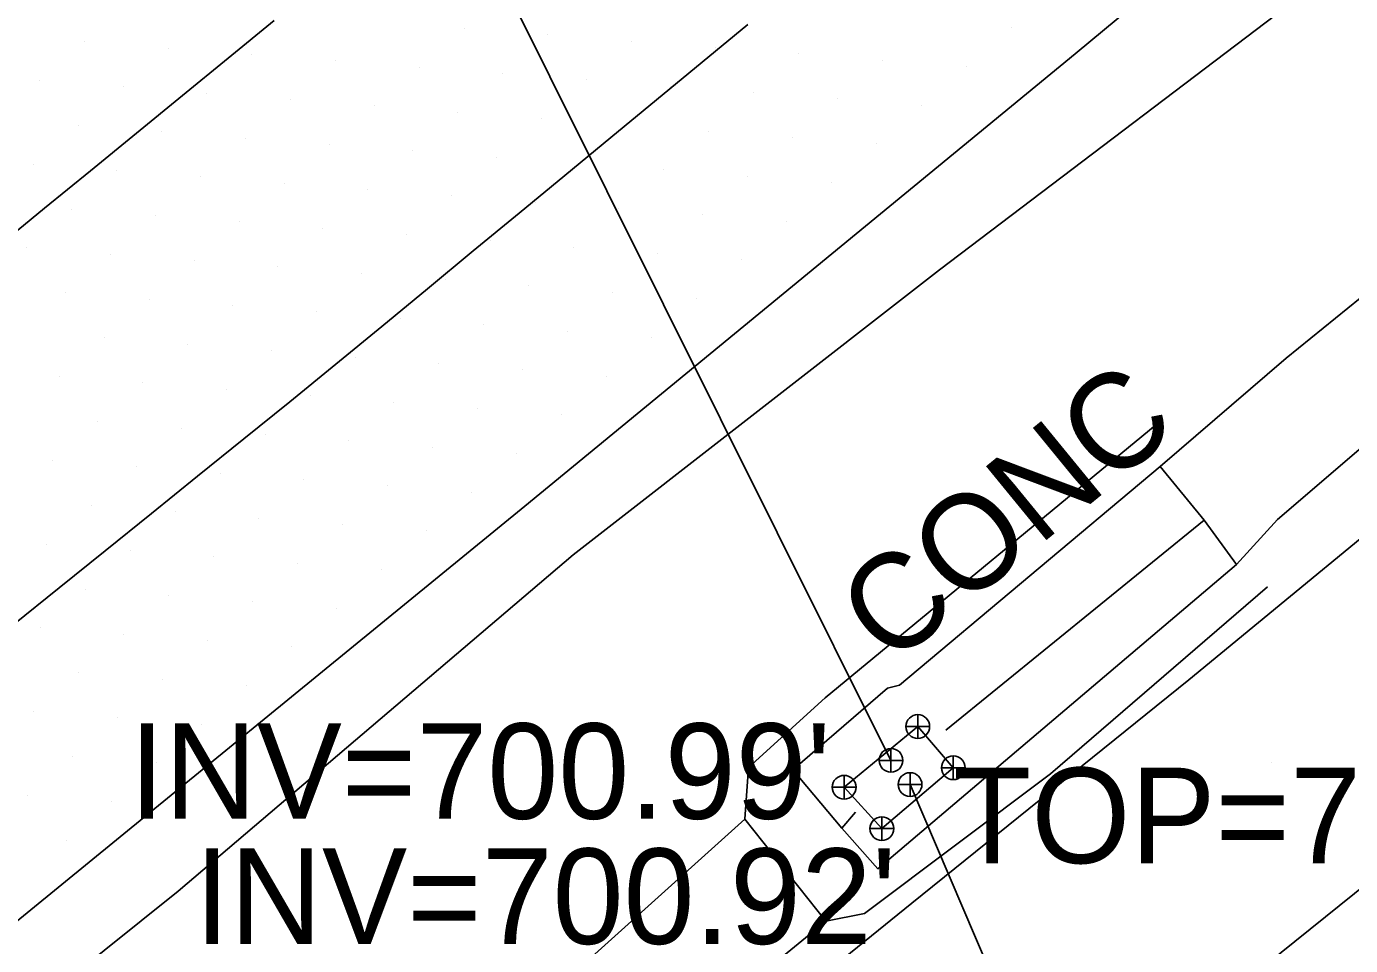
# Model space of a CAD drawing. Extents: x 1548934 to 1561348, y 809680 to 824075.
# Drawn here: x 1551457.5 to 1551513.3, y 810442.3 to 810481 of the extents above; entities that cross this region are included whole.
import ezdxf

# ---------------------------------------------------------------- set-up
doc = ezdxf.new("R2010")
doc.units = 0
for name, color, linetype in [('Default', 7, 'Continuous'), ('E_NCDOT_Vertical_Profile_Ground_Line', 7, 'Continuous'), ('Exist DTM QL2 LIDAR Elevation Point', 7, 'Continuous'), ('Exist DTM Scan Elevation Point', 7, 'Continuous'), ('Exist Guardrail Cable Guide Rail', 7, 'Continuous'), ('Exist Structure Minor Drop Inlet Top Elevation', 7, 'Continuous'), ('Exist Structure Minor Paved Ditch or Gutter', 7, 'Continuous'), ('Exist Structure Minor Paved Ditch or Gutter Text', 7, 'Continuous'), ('Exist Structure Minor Pipes RCP 15 Inch Invert Elevation', 7, 'Continuous'), ('P_RDY_Dimension', 7, 'Continuous'), ('P_RDY_Terminator_Cell', 7, 'Continuous'), ('PH Exist DTM Breakline', 7, 'Continuous'), ('Sheet_Matchline_Text', 7, 'Continuous')]:
    doc.layers.add(name, color=color, linetype=linetype)

# ---------------------------------------------------------------- blocks, each defined once
blk = doc.blocks.new('SurveyPointCell')
at = {"layer": 'Default'}
for p, q in [((-0.5, 0), (0.5, 0)), ((0, -0.5), (0, 0.5))]:
    blk.add_line(p, q, dxfattribs=at)
blk.add_circle((0, 0), 0.5, dxfattribs=at)

msp = doc.modelspace()

# ---------------------------------------------------------------- linework, layer by layer
at = {"layer": 'E_NCDOT_Vertical_Profile_Ground_Line'}
msp.add_lwpolyline([(1551420.508, 810413.559), (1551431.924, 810422.797), (1551455.236, 810441.768), (1551478.523, 810460.78), (1551501.702, 810479.825), (1551524.839, 810499.022), (1551547.879, 810518.234), (1551570.873, 810537.502), (1551593.819, 810556.903), (1551616.71, 810576.292), (1551639.811, 810595.486)], dxfattribs=at)
at = {"layer": 'Exist DTM QL2 LIDAR Elevation Point'}
for p, q in [((1551479.977, 810449.967), (1551479.977, 810449.967)), ((1551509.98, 810449.967), (1551509.98, 810449.967))]:
    msp.add_line(p, q, dxfattribs=at)
at = {"layer": 'Exist DTM Scan Elevation Point'}
for p, q in [((1551475.968, 810480.891), (1551475.968, 810480.891)), ((1551479.493, 810480.623), (1551479.493, 810480.623)), ((1551499.018, 810480.915), (1551499.018, 810480.915)), ((1551459.971, 810480.332), (1551459.971, 810480.332)), ((1551463.496, 810480.064), (1551463.496, 810480.064)), ((1551483.019, 810480.355), (1551483.019, 810480.355)), ((1551486.544, 810480.088), (1551486.544, 810480.088)), ((1551467.021, 810479.797), (1551467.021, 810479.797)), ((1551470.546, 810479.529), (1551470.546, 810479.529)), ((1551490.069, 810479.82), (1551490.069, 810479.82)), ((1551493.595, 810479.553), (1551493.595, 810479.553)), ((1551474.072, 810479.262), (1551474.072, 810479.262)), ((1551477.597, 810478.994), (1551477.597, 810478.994)), ((1551497.121, 810479.286), (1551497.121, 810479.286)), ((1551458.074, 810478.703), (1551458.074, 810478.703)), ((1551461.6, 810478.435), (1551461.6, 810478.435)), ((1551481.122, 810478.726), (1551481.122, 810478.726)), ((1551484.648, 810478.459), (1551484.648, 810478.459)), ((1551465.125, 810478.168), (1551465.125, 810478.168)), ((1551468.65, 810477.9), (1551468.65, 810477.9)), ((1551488.173, 810478.192), (1551488.173, 810478.192)), ((1551491.699, 810477.924), (1551491.699, 810477.924)), ((1551472.175, 810477.633), (1551472.175, 810477.633)), ((1551475.701, 810477.365), (1551475.701, 810477.365)), ((1551495.225, 810477.657), (1551495.225, 810477.657)), ((1551459.703, 810476.806), (1551459.703, 810476.806)), ((1551479.226, 810477.098), (1551479.226, 810477.098)), ((1551482.751, 810476.83), (1551482.751, 810476.83)), ((1551463.228, 810476.539), (1551463.228, 810476.539)), ((1551466.754, 810476.271), (1551466.754, 810476.271)), ((1551486.277, 810476.563), (1551486.277, 810476.563)), ((1551489.803, 810476.296), (1551489.803, 810476.296)), ((1551493.329, 810476.029), (1551493.329, 810476.029)), ((1551470.279, 810476.004), (1551470.279, 810476.004)), ((1551473.804, 810475.736), (1551473.804, 810475.736)), ((1551477.329, 810475.469), (1551477.329, 810475.469)), ((1551457.807, 810475.177), (1551457.807, 810475.177)), ((1551461.332, 810474.91), (1551461.332, 810474.91)), ((1551480.855, 810475.201), (1551480.855, 810475.201)), ((1551484.381, 810474.934), (1551484.381, 810474.934)), ((1551464.857, 810474.642), (1551464.857, 810474.642)), ((1551468.382, 810474.375), (1551468.382, 810474.375)), ((1551487.906, 810474.667), (1551487.906, 810474.667)), ((1551491.432, 810474.4), (1551491.432, 810474.4)), ((1551471.908, 810474.107), (1551471.908, 810474.107)), ((1551475.433, 810473.84), (1551475.433, 810473.84)), ((1551459.436, 810473.281), (1551459.436, 810473.281)), ((1551478.958, 810473.572), (1551478.958, 810473.572)), ((1551482.484, 810473.305), (1551482.484, 810473.305)), ((1551462.961, 810473.013), (1551462.961, 810473.013)), ((1551466.486, 810472.746), (1551466.486, 810472.746)), ((1551486.01, 810473.038), (1551486.01, 810473.038)), ((1551489.536, 810472.771), (1551489.536, 810472.771)), ((1551470.011, 810472.478), (1551470.011, 810472.478)), ((1551473.537, 810472.211), (1551473.537, 810472.211)), ((1551457.539, 810471.652), (1551457.539, 810471.652)), ((1551477.062, 810471.943), (1551477.062, 810471.943)), ((1551480.588, 810471.676), (1551480.588, 810471.676)), ((1551461.064, 810471.384), (1551461.064, 810471.384)), ((1551464.59, 810471.117), (1551464.59, 810471.117)), ((1551484.113, 810471.409), (1551484.113, 810471.409)), ((1551487.639, 810471.142), (1551487.639, 810471.142)), ((1551468.115, 810470.849), (1551468.115, 810470.849)), ((1551471.64, 810470.582), (1551471.64, 810470.582)), ((1551475.166, 810470.314), (1551475.166, 810470.314)), ((1551478.691, 810470.047), (1551478.691, 810470.047)), ((1551459.168, 810469.755), (1551459.168, 810469.755)), ((1551462.693, 810469.488), (1551462.693, 810469.488)), ((1551482.217, 810469.78), (1551482.217, 810469.78)), ((1551485.743, 810469.513), (1551485.743, 810469.513)), ((1551466.219, 810469.22), (1551466.219, 810469.22)), ((1551469.744, 810468.953), (1551469.744, 810468.953)), ((1551473.269, 810468.685), (1551473.269, 810468.685)), ((1551476.795, 810468.418), (1551476.795, 810468.418)), ((1551460.797, 810467.859), (1551460.797, 810467.859)), ((1551480.321, 810468.151), (1551480.321, 810468.151)), ((1551483.846, 810467.884), (1551483.846, 810467.884)), ((1551464.322, 810467.591), (1551464.322, 810467.591)), ((1551467.847, 810467.324), (1551467.847, 810467.324)), ((1551471.373, 810467.056), (1551471.373, 810467.056)), ((1551474.899, 810466.789), (1551474.899, 810466.789)), ((1551458.9, 810466.23), (1551458.9, 810466.23)), ((1551478.424, 810466.522), (1551478.424, 810466.522)), ((1551481.95, 810466.255), (1551481.95, 810466.255)), ((1551462.426, 810465.962), (1551462.426, 810465.962)), ((1551465.951, 810465.695), (1551465.951, 810465.695)), ((1551469.477, 810465.427), (1551469.477, 810465.427)), ((1551473.002, 810465.16), (1551473.002, 810465.16)), ((1551476.528, 810464.893), (1551476.528, 810464.893)), ((1551460.529, 810464.333), (1551460.529, 810464.333)), ((1551480.053, 810464.626), (1551480.053, 810464.626)), ((1551464.055, 810464.066), (1551464.055, 810464.066)), ((1551467.58, 810463.798), (1551467.58, 810463.798)), ((1551471.106, 810463.531), (1551471.106, 810463.531)), ((1551474.631, 810463.264), (1551474.631, 810463.264)), ((1551458.633, 810462.704), (1551458.633, 810462.704)), ((1551478.157, 810462.997), (1551478.157, 810462.997)), ((1551462.158, 810462.437), (1551462.158, 810462.437)), ((1551465.684, 810462.17), (1551465.684, 810462.17)), ((1551469.209, 810461.902), (1551469.209, 810461.902)), ((1551472.735, 810461.635), (1551472.735, 810461.635)), ((1551476.261, 810461.368), (1551476.261, 810461.368)), ((1551460.262, 810460.808), (1551460.262, 810460.808)), ((1551463.787, 810460.541), (1551463.787, 810460.541)), ((1551467.313, 810460.273), (1551467.313, 810460.273)), ((1551470.839, 810460.006), (1551470.839, 810460.006)), ((1551474.364, 810459.739), (1551474.364, 810459.739)), ((1551458.365, 810459.179), (1551458.365, 810459.179)), ((1551461.891, 810458.912), (1551461.891, 810458.912)), ((1551465.417, 810458.644), (1551465.417, 810458.644)), ((1551468.942, 810458.377), (1551468.942, 810458.377)), ((1551472.468, 810458.11), (1551472.468, 810458.11)), ((1551459.994, 810457.283), (1551459.994, 810457.283)), ((1551463.52, 810457.015), (1551463.52, 810457.015)), ((1551467.046, 810456.748), (1551467.046, 810456.748)), ((1551470.572, 810456.481), (1551470.572, 810456.481)), ((1551458.098, 810455.654), (1551458.098, 810455.654)), ((1551461.624, 810455.387), (1551461.624, 810455.387)), ((1551465.15, 810455.119), (1551465.15, 810455.119)), ((1551468.675, 810454.852), (1551468.675, 810454.852)), ((1551459.727, 810453.758), (1551459.727, 810453.758)), ((1551463.253, 810453.49), (1551463.253, 810453.49)), ((1551466.779, 810453.223), (1551466.779, 810453.223)), ((1551457.831, 810452.129), (1551457.831, 810452.129)), ((1551461.357, 810451.862), (1551461.357, 810451.862)), ((1551464.883, 810451.594), (1551464.883, 810451.594)), ((1551459.46, 810450.233), (1551459.46, 810450.233)), ((1551462.986, 810449.966), (1551462.986, 810449.966)), ((1551457.564, 810448.604), (1551457.564, 810448.604)), ((1551461.09, 810448.337), (1551461.09, 810448.337)), ((1551459.194, 810446.708), (1551459.194, 810446.708))]:
    msp.add_line(p, q, dxfattribs=at)
at = {"layer": 'Exist Guardrail Cable Guide Rail'}
msp.add_lwpolyline([(1551645.067, 810568.012), (1551633.432, 810558.34), (1551621.822, 810548.837), (1551610.482, 810539.585), (1551598.849, 810530.042), (1551587.485, 810520.244), (1551575.884, 810510.524), (1551564.405, 810500.869), (1551552.918, 810491.413), (1551541.303, 810481.922), (1551529.638, 810472.396), (1551518.006, 810462.924), (1551506.503, 810453.466), (1551494.828, 810444.049), (1551483.162, 810434.602), (1551471.543, 810425.115), (1551459.946, 810415.577), (1551448.331, 810406.085), (1551436.847, 810396.877), (1551435.436, 810395.766)], dxfattribs=at)
at = {"layer": 'Exist Structure Minor Paved Ditch or Gutter'}
msp.add_lwpolyline([(1551489.808, 810449.675), (1551491.88, 810447.21), (1551493.39, 810445.505), (1551508.512, 810458.318), (1551507.146, 810460.19), (1551505.295, 810462.443), (1551494.308, 810453.229), (1551493.798, 810453.106)], close=True, dxfattribs=at)
at = {"layer": 'P_RDY_Dimension'}
msp.add_lwpolyline([(1551491.974, 810448.935), (1551495.075, 810451.494), (1551496.573, 810449.758), (1551493.563, 810447.193)], close=True, dxfattribs=at)
at = {"layer": 'P_RDY_Terminator_Cell'}
for points in [[(1551467.959, 810481.234), (1551466.026, 810479.649), (1551464.093, 810478.064), (1551462.157, 810476.482), (1551460.219, 810474.902), (1551458.282, 810473.323), (1551456.344, 810471.743)], [(1551487.923, 810481.067), (1551485.995, 810479.476), (1551484.066, 810477.886), (1551482.137, 810476.295), (1551480.208, 810474.705), (1551478.279, 810473.115), (1551476.35, 810471.524), (1551474.421, 810469.934), (1551472.493, 810468.343), (1551470.564, 810466.753), (1551468.626, 810465.174), (1551466.68, 810463.604), (1551464.733, 810462.035), (1551462.787, 810460.466), (1551460.841, 810458.897), (1551458.895, 810457.328), (1551456.949, 810455.758)]]:
    msp.add_lwpolyline(points, dxfattribs=at)
at = {"layer": 'PH Exist DTM Breakline'}
for points in [[(1551417.883, 810407.398), (1551432.392, 810419.235), (1551448.388, 810432.126), (1551463.908, 810444.556), (1551480.556, 810458.727), (1551495.998, 810470.721), (1551512.779, 810483.455), (1551526.124, 810494.877), (1551540.797, 810506.743), (1551554.488, 810518.26), (1551567.602, 810529.513), (1551583.151, 810542.273), (1551597.076, 810551.659), (1551607.705, 810560.571), (1551621.142, 810571.735), (1551639.856, 810587.953), (1551647.753, 810594.047)], [(1551651.205, 810580.522), (1551634.978, 810567.87), (1551617.697, 810553.269), (1551602.678, 810542.212), (1551586.74, 810528.584), (1551569.406, 810514.46), (1551549.364, 810497.885), (1551539.556, 810489.121), (1551521.511, 810475.85), (1551510.594, 810467.01), (1551505.295, 810462.443)], [(1551508.512, 810458.318), (1551510.226, 810460.21), (1551518.079, 810466.939), (1551534.133, 810479.588), (1551547.348, 810489.741), (1551562.128, 810501.878), (1551582.032, 810517.617), (1551599.809, 810532.54), (1551619.269, 810544.946), (1551633.433, 810554.563), (1551653.907, 810568.703)], [(1551658.016, 810565.912), (1551634.484, 810546.871), (1551612.397, 810528.841), (1551592.062, 810511.696), (1551567.719, 810489.454), (1551545.048, 810470.284), (1551524.68, 810453.477), (1551509.741, 810441.458), (1551485.853, 810422.028), (1551464.135, 810403.78), (1551440.534, 810384.685), (1551434.664, 810379.828)], [(1551505.402, 810464.432), (1551491.178, 810452.697), (1551487.94, 810449.767), (1551487.786, 810447.586), (1551491.205, 810443.3), (1551492.838, 810443.62), (1551500.675, 810449.498), (1551509.806, 810457.381)], [(1551507.146, 810460.19), (1551496.264, 810451.334)], [(1551487.786, 810447.586), (1551479.359, 810440.013), (1551464.818, 810430.639), (1551446.691, 810412.855), (1551430.633, 810399.563), (1551408.198, 810381.612)], [(1551491.88, 810447.21), (1551492.456, 810447.881)], [(1551446.691, 810412.855), (1551458.768, 810418.846), (1551471.125, 810426.829), (1551481.195, 810435.104), (1551491.205, 810443.3)]]:
    msp.add_lwpolyline(points, dxfattribs=at)
at = {"layer": 'Sheet_Matchline_Text'}
for points in [[(1551493.948, 810450.069), (1551458.031, 810522.084)], [(1551494.751, 810449.049), (1551526.927, 810373.732)]]:
    msp.add_lwpolyline(points, dxfattribs=at)

# ---------------------------------------------------------------- block references
at = {"layer": 'Default'}
for p in [(1551495.075, 810451.494), (1551493.948, 810450.069), (1551496.573, 810449.758), (1551491.974, 810448.935), (1551494.751, 810449.049), (1551493.563, 810447.193)]:
    msp.add_blockref('SurveyPointCell', p, dxfattribs=at)

# ---------------------------------------------------------------- texts
at = {"layer": 'Exist Structure Minor Drop Inlet Top Elevation'}
msp.add_text("TOP=706.21'", height=4.02, rotation=360, dxfattribs=at).set_placement((1551496.573, 810445.738))
at = {"layer": 'Exist Structure Minor Paved Ditch or Gutter Text'}
msp.add_text('CONC', height=4.02, rotation=39.2997, dxfattribs=at).set_placement((1551493.916, 810453.958))
at = {"layer": 'Exist Structure Minor Pipes RCP 15 Inch Invert Elevation'}
for s, p in [("INV=700.99'", (1551461.851, 810447.606)), ("INV=700.92'", (1551464.6, 810442.337))]:
    msp.add_text(s, height=4.02, rotation=360, dxfattribs=at).set_placement(p)

doc.saveas('drawing.dxf')
